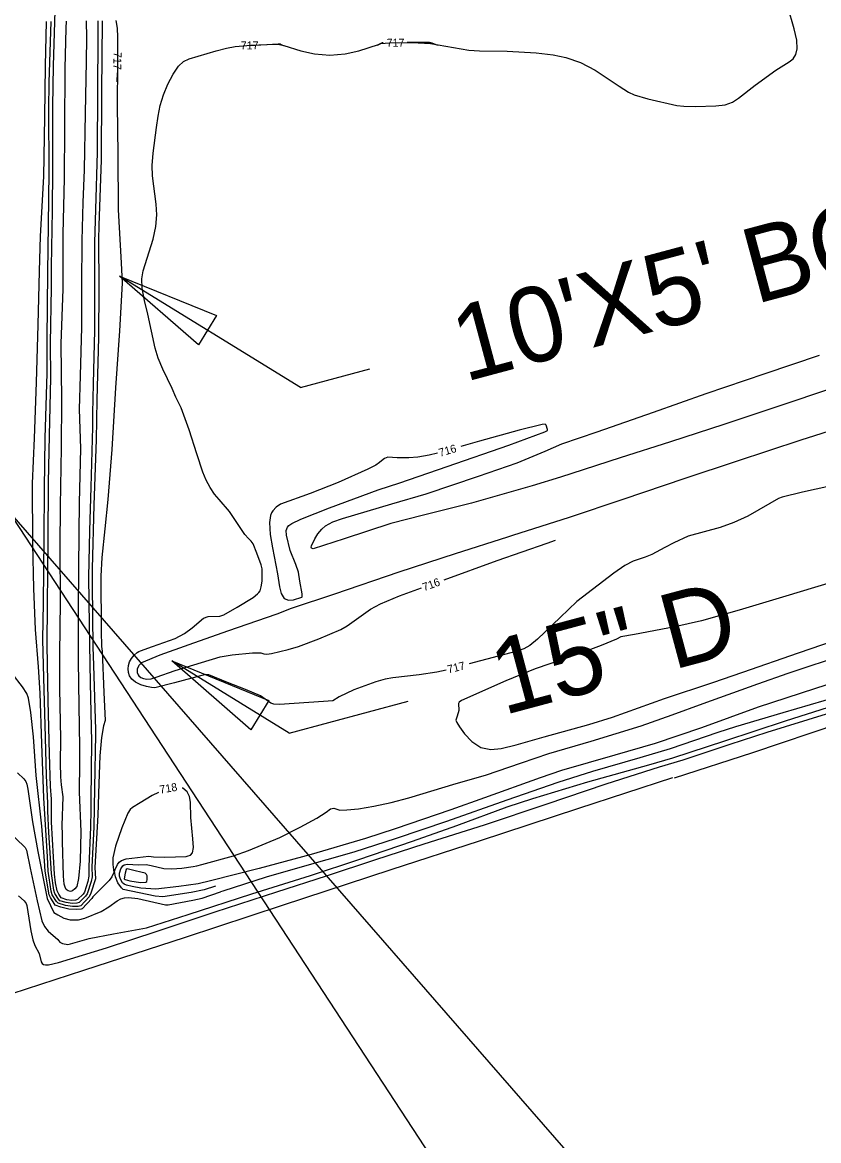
# Model space of a CAD drawing. Extents: x -361782338 to 28259792, y -263199453 to 8342113.
# Drawn here: x 1403847 to 1404244, y 576353 to 576912 of the extents above; entities that cross this region are included whole.
import ezdxf

# ---------------------------------------------------------------- set-up
doc = ezdxf.new("R2010")
doc.units = 0
for name, color, linetype in [('DT_X_Contour_Minor', 7, 'Continuous'), ('Level 14', 7, 'Continuous'), ('Level 19', 7, 'Continuous'), ('Level 40', 7, 'Continuous')]:
    doc.layers.add(name, color=color, linetype=linetype)

msp = doc.modelspace()

# ---------------------------------------------------------------- linework, layer by layer
at = {"layer": 'DT_X_Contour_Minor'}
for points in [[(1403884.36, 576912.33), (1403884.32, 576904.28), (1403884.16, 576877.16), (1403883.92, 576846.72), (1403883.03, 576818.05), (1403882.55, 576801.44), (1403882.6, 576772.64), (1403882.57, 576757.74), (1403881.87, 576730.96), (1403881.62, 576716.27), (1403881.61, 576709.28), (1403880.76, 576679.2), (1403880.08, 576657.35), (1403879.66, 576634.3), (1403879.9, 576610.47), (1403880.37, 576581.24), (1403881.17, 576552.15), (1403880.71, 576523.06), (1403880.85, 576518.07), (1403880.59, 576509.33), (1403879.73, 576489.71), (1403879.82, 576484.8), (1403879.32, 576482.14), (1403877.63, 576476.86), (1403876.9, 576475.86), (1403874.2, 576473.17), (1403873.16, 576472.81), (1403871.24, 576472.72), (1403868.84, 576473.06), (1403865.97, 576474.1), (1403864.78, 576475.79), (1403863.92, 576477.46), (1403863.17, 576481.55), (1403862.63, 576485.88), (1403861.15, 576511.91), (1403861.2, 576523.26), (1403860.67, 576529.64), (1403860.07, 576546.06), (1403859.55, 576572.43), (1403858.89, 576600.21), (1403859.22, 576620.7), (1403859.54, 576652.76), (1403859.67, 576681.58), (1403860.06, 576704.99), (1403860.76, 576733.86), (1403860.71, 576751.16), (1403861.07, 576778.81), (1403861.17, 576789.45), (1403861.6, 576817.44), (1403861.85, 576838.38), (1403861.82, 576869.5), (1403862.2, 576889.83), (1403863.02, 576917.3)], [(1403964.65, 576626.61), (1403965.31, 576627.48), (1403965.92, 576629.5), (1403966.28, 576632.33), (1403966.43, 576635.5), (1403966.3, 576638.36), (1403965.85, 576640.46), (1403963.61, 576646.32), (1403961.9, 576650.93), (1403960.82, 576652.32), (1403959.46, 576653.61), (1403957.69, 576655.65), (1403950.11, 576667.07), (1403944.88, 576673.03), (1403942.5, 576675.82), (1403940.34, 576679.05), (1403938.41, 576682.73), (1403936.72, 576686.75), (1403933.71, 576695.92), (1403929.94, 576707.86), (1403925.98, 576718.96), (1403923.93, 576722.94), (1403923.17, 576724.25), (1403921.39, 576728.58), (1403916.72, 576738.23), (1403914.47, 576743.66), (1403912.99, 576748.64), (1403909.25, 576765.72), (1403907.62, 576772.55), (1403906.49, 576778.64), (1403906.29, 576783.31), (1403906.96, 576787.28), (1403911.99, 576803.19), (1403913.32, 576809.49), (1403913.75, 576815.37), (1403913.49, 576820.75), (1403911.6, 576834.88), (1403911.45, 576840.08), (1403911.84, 576846.16), (1403913.5, 576859.02), (1403914.38, 576864.72), (1403915.46, 576870.01), (1403917.01, 576875.25), (1403919.23, 576880.65), (1403921.86, 576885.67), (1403924.55, 576889.61), (1403927.08, 576891.98), (1403929.85, 576893.31), (1403943.44, 576897.29), (1403948.53, 576898.59), (1403952.85, 576899.39), (1403960.67, 576900.06), (1403972.77, 576900.6), (1403975.09, 576900.47), (1403977.21, 576899.97), (1403985.63, 576897.33), (1403992.45, 576895.8), (1404000.1, 576895.11), (1404007.8, 576895.8), (1404014.71, 576897.32), (1404024.43, 576900.43), (1404025.57, 576900.9), (1404030.03, 576901.24), (1404041.26, 576901.39), (1404050.48, 576900.95), (1404069.63, 576897.69), (1404074.9, 576897.35), (1404088.73, 576897.06), (1404103.28, 576896.38), (1404111.62, 576895.36), (1404118.06, 576893.99), (1404125.29, 576891.47), (1404132.68, 576887.59), (1404144.62, 576879.6), (1404149.27, 576876.62), (1404152.18, 576875.33), (1404158.94, 576873.39), (1404173.48, 576870.04), (1404176.97, 576869.66), (1404182.84, 576869.52), (1404192.9, 576869.75), (1404197.68, 576870.4), (1404201.25, 576871.65), (1404204.3, 576873.63), (1404212.65, 576880.19), (1404222.98, 576887.58), (1404229.58, 576891.73), (1404231.57, 576893.35), (1404232.96, 576895.41), (1404233.61, 576898.34), (1404233.32, 576902.57), (1404232, 576908.22), (1404228.93, 576919.34)], [(1403893.32, 576912.46), (1403893.86, 576908.67), (1403894.13, 576904.07), (1403894.04, 576890.51), (1403893.91, 576870.17), (1403894.23, 576845.71), (1403894.45, 576817.91), (1403895.94, 576791.31), (1403896.47, 576781.23), (1403895.03, 576757.39), (1403893.14, 576728.83), (1403891.34, 576698.04), (1403889.25, 576673.14), (1403887.76, 576658.39), (1403886.21, 576644.17), (1403885.78, 576634.77), (1403885.96, 576607.37), (1403886.04, 576599.6), (1403886.48, 576597.33), (1403887.23, 576576.6), (1403887.89, 576562.6), (1403887.14, 576560.05), (1403886.12, 576554.11), (1403885.21, 576545.05), (1403884.7, 576531.11), (1403884.21, 576515.37), (1403882.7, 576489.2), (1403883.03, 576483.47), (1403880.75, 576476.31), (1403880.02, 576474.6), (1403875.71, 576470.11), (1403874.48, 576469.75), (1403871.69, 576469.69), (1403868.07, 576470.2), (1403864.43, 576471.32), (1403863.64, 576472.13), (1403861.5, 576475.52), (1403861.04, 576477.43), (1403859.54, 576487.29), (1403859.12, 576494.45), (1403857.26, 576523.99), (1403856.34, 576551.02), (1403855.53, 576576.32), (1403854.7, 576589.54), (1403853.21, 576608.11), (1403852.24, 576628.69), (1403851.85, 576650.85), (1403851.58, 576681.16), (1403852.64, 576703.71), (1403853.63, 576731.52), (1403854.4, 576760.3), (1403855.06, 576787.24), (1403855.7, 576804.65), (1403857.32, 576834.47), (1403857.73, 576864.36), (1403858.2, 576889.74), (1403858.66, 576911.96)], [(1403886.45, 576912.36), (1403886.28, 576894.22), (1403886.19, 576876.96), (1403885.87, 576842.84), (1403884.83, 576809.99), (1403884.69, 576803.05), (1403884.74, 576778.83), (1403884.61, 576754.03), (1403883.83, 576722.91), (1403883.38, 576702.96), (1403882.35, 576670.47), (1403881.37, 576638.44), (1403881.39, 576630.37), (1403881.81, 576599.25), (1403882.04, 576590.28), (1403883.19, 576557.97), (1403883.19, 576555.64), (1403882.69, 576528.92), (1403882.2, 576509.33), (1403881.21, 576489.45), (1403881.49, 576484.54), (1403881, 576482.2), (1403879, 576476.04), (1403878.17, 576474.91), (1403874.96, 576471.64), (1403873.82, 576471.28), (1403871.46, 576471.21), (1403868.45, 576471.63), (1403865.38, 576472.59), (1403864.64, 576473.3), (1403862.8, 576476.22), (1403862.38, 576477.9), (1403861.1, 576486.22), (1403859.84, 576506.61), (1403859.31, 576517.37), (1403859.38, 576521.26), (1403858.63, 576535.2), (1403858.01, 576560.26), (1403857.26, 576584), (1403856.8, 576603.13), (1403857.09, 576621.48), (1403857.54, 576653.89), (1403857.64, 576678.29), (1403857.97, 576703.79), (1403858.92, 576736.27), (1403858.97, 576753.05), (1403859.24, 576786.75), (1403859.6, 576810.33), (1403859.92, 576836.88), (1403859.8, 576868.15), (1403860.01, 576881.43), (1403860.92, 576911.99)], [(1403878.48, 576912.25), (1403878.54, 576903.78), (1403878.45, 576891.99), (1403877.96, 576866.15), (1403877.47, 576837.79), (1403876.86, 576821.44), (1403876.22, 576802.58), (1403876.12, 576780.28), (1403876.19, 576759.14), (1403875.38, 576734.9), (1403874.9, 576718.28), (1403875.63, 576698.54), (1403875.02, 576671.43), (1403874.85, 576656.6), (1403874.7, 576638.11), (1403874.43, 576618.15), (1403874.45, 576592.48), (1403874.76, 576569.92), (1403875.14, 576549.46), (1403875.1, 576541.67), (1403875.03, 576526.78), (1403875.74, 576507.12), (1403875.4, 576492.38), (1403874.55, 576483.66), (1403873.72, 576479.67), (1403872.85, 576478.47), (1403871.55, 576477.54), (1403870.55, 576477.27), (1403869.43, 576477.55), (1403868.49, 576478.21), (1403867.88, 576479.37), (1403867.53, 576480.87), (1403867.2, 576484.83), (1403866.62, 576502.24), (1403866.55, 576505.73), (1403866.54, 576510.18), (1403866.91, 576524.51), (1403866.18, 576530.48), (1403865.74, 576534.45), (1403865.69, 576541.29), (1403865.74, 576553.52), (1403865.24, 576578.63), (1403865.24, 576595.93), (1403865.62, 576621.8), (1403865.53, 576649.36), (1403865.7, 576669.88), (1403866.15, 576698.99), (1403866.36, 576722.94), (1403866.01, 576751.07), (1403866.97, 576778.26), (1403867, 576805.86), (1403867.61, 576833.53), (1403867.78, 576858.87), (1403868.04, 576888.4), (1403868.4, 576908.63), (1403868.55, 576912.1)], [(1403960, 576900), (1403974.39, 576900.85), (1403974.69, 576900.85), (1403974.99, 576900.81), (1403975.27, 576900.73), (1403975.55, 576900.62), (1403976.83, 576900)], [(1404026.87, 576901.27), (1404026.68, 576901.27), (1404026.47, 576901.25), (1404026.27, 576901.22), (1404026.08, 576901.17), (1404025.88, 576901.09), (1404025.13, 576900.76), (1404025.07, 576900.72), (1404025, 576900.69), (1404024.94, 576900.65), (1404024.88, 576900.6), (1404024.7, 576900.44), (1404024.66, 576900.41), (1404024.62, 576900.38), (1404024.57, 576900.35), (1404024.53, 576900.33), (1404023.75, 576900)], [(1404054.03, 576899.99), (1404051.2, 576901.08), (1404050.59, 576901.29), (1404049.97, 576901.43), (1404049.34, 576901.51), (1404048.7, 576901.53), (1404038.86, 576901.42)], [(1403893.88, 576886.39), (1403893.73, 576881.81)], [(1404249.74, 576728.19), (1404225.37, 576720.01), (1404196.87, 576710.58), (1404170.25, 576701.97), (1404145.18, 576693.96), (1404120.97, 576686.1), (1404115.35, 576684.17), (1404101.21, 576679.91), (1404070.85, 576671.32), (1404046.9, 576665.34), (1404030.62, 576661.08), (1404007.35, 576653.44), (1403991.76, 576648.35), (1403991.05, 576648.75), (1403990.81, 576649.26), (1403990.94, 576649.93), (1403992.65, 576653.42), (1403994.24, 576655.95), (1403996.09, 576658.3), (1403998.02, 576660), (1404001.7, 576661.94), (1404006.5, 576663.61), (1404031.1, 576670.87), (1404048.34, 576675.99), (1404074.47, 576684.83), (1404093.68, 576691.47), (1404107.71, 576697.3), (1404116.09, 576700.83), (1404133.67, 576706.98), (1404161.78, 576716.79), (1404188.09, 576725.99), (1404217.54, 576736.11), (1404244.66, 576745.26)], [(1404343.7, 576737.72), (1404328.98, 576732.82), (1404301.91, 576724.01), (1404287.5, 576719.5), (1404263.17, 576711.61), (1404235.45, 576702.71), (1404203.09, 576692.14), (1404177.51, 576683.51), (1404146.48, 576673.07), (1404119.69, 576664.09), (1404091.39, 576655.12), (1404088.86, 576654.3)], [(1403985.19, 576632.29), (1403984.45, 576636.74), (1403983.16, 576640.65), (1403980.28, 576647.55), (1403978.56, 576655.2), (1403978.35, 576657.52), (1403978.94, 576659.2), (1403979.74, 576660.12), (1403981.11, 576661.1), (1403985.62, 576663.21), (1403999.99, 576668.99), (1404024.26, 576677.89), (1404035.11, 576681.45), (1404058.79, 576689.56), (1404089.51, 576700.28), (1404107.52, 576706.9), (1404108.8, 576707.57), (1404108.85, 576708.06), (1404108.13, 576710.29), (1404107.74, 576710.73), (1404106.14, 576710.61), (1404094.67, 576707.73), (1404074.87, 576702.21), (1404065.53, 576699.51)], [(1404053.97, 576696.28), (1404049.82, 576695.24), (1404044.08, 576694.25), (1404039.6, 576693.86), (1404033.78, 576693.91), (1404029.04, 576694.18), (1404027.5, 576693.59), (1404025.89, 576692.37), (1404025.01, 576691.55), (1404023.11, 576690.27), (1404019.13, 576688.17), (1404004.28, 576681.59), (1403990.27, 576676.07), (1403975.53, 576670.83), (1403973.31, 576669.2), (1403971.7, 576667.44), (1403971.01, 576666.38), (1403970.49, 576665.04), (1403970.1, 576661.57), (1403970.3, 576655.6), (1403971.46, 576648.91), (1403974.04, 576635.97), (1403974.98, 576629.46)], [(1404265.11, 576683.16), (1404236.15, 576676.75), (1404226.06, 576674.23), (1404224.23, 576673.56), (1404219.95, 576671.1), (1404208.92, 576664.77), (1404201.99, 576661.54), (1404195.05, 576659.15), (1404179.2, 576654.73), (1404171.98, 576651.4), (1404167.46, 576649.17), (1404161, 576645.68), (1404157.72, 576644.21), (1404151.59, 576642.2), (1404147.45, 576640.04), (1404141.96, 576636.25), (1404123.56, 576622.13), (1404115.23, 576614.16), (1404103.82, 576603.27), (1404100.08, 576600.15), (1404097, 576598.45), (1404093.12, 576597.18), (1404069.82, 576590.89)], [(1404088.86, 576654.3), (1404062.82, 576645.94), (1404034.67, 576636.74), (1404002.44, 576625.8), (1403980.81, 576618.62), (1403973.71, 576615.84), (1403949.1, 576607.23), (1403929.7, 576600.39), (1403915.31, 576595.36), (1403906.11, 576591.51), (1403904.73, 576590.07), (1403904.6, 576589.76)], [(1404057.21, 576632.97), (1404083.8, 576642.59), (1404108.64, 576651.26), (1404112.92, 576652.74)], [(1403974.98, 576629.46), (1403974.99, 576629.38), (1403975.84, 576626.04), (1403977.3, 576623.65), (1403979.54, 576622.77), (1403982.06, 576622.96), (1403986.21, 576624.2), (1403986.4, 576624.5), (1403986.26, 576625.87), (1403985.19, 576632.29)], [(1404258.2, 576633.89), (1404227.89, 576624.76), (1404204.67, 576617.85), (1404185.83, 576612.39), (1404172.54, 576609.45), (1404152.34, 576605.62), (1404145.51, 576604.46), (1404143.27, 576603.34), (1404135.65, 576600.19), (1404124.16, 576595.86), (1404102.69, 576588.46), (1404088.12, 576582.55), (1404065.99, 576572.63), (1404064.7, 576571.88), (1404064.41, 576571.21), (1404064.63, 576567.56), (1404063.79, 576564.83), (1404063.12, 576562.86), (1404063.53, 576561.66), (1404064.88, 576559.48), (1404067.44, 576555.98), (1404071.08, 576552.13), (1404075.58, 576549.22), (1404080.64, 576548.2), (1404085.67, 576548.59), (1404093.27, 576550.47), (1404107.23, 576554.43), (1404129.46, 576560.57), (1404141.31, 576564.35), (1404167.24, 576573.66), (1404191.45, 576581.68), (1404206.47, 576586.77), (1404234.28, 576596.46), (1404258, 576604.67)], [(1403904.5, 576585.42), (1403904.81, 576584.94), (1403905.71, 576584.21), (1403907.03, 576583.64), (1403908.78, 576583.36), (1403910.94, 576583.54), (1403913.48, 576584.26), (1403922.91, 576587.66), (1403945.46, 576594.48), (1403951.4, 576595.5), (1403961.59, 576596.5), (1403965.67, 576596.42), (1403967.24, 576595.94), (1403968.61, 576595.87), (1403970.99, 576596.14), (1403979.31, 576598.1), (1403984.46, 576599.69), (1403994.59, 576603.52), (1404005.71, 576608.13), (1404008.8, 576609.93), (1404020.44, 576618.24), (1404025.42, 576620.87), (1404035, 576624.88), (1404045.94, 576628.87)], [(1403904.77, 576597.06), (1403905.61, 576597.52), (1403911.51, 576599.56), (1403922.93, 576603.67), (1403927.63, 576606.1), (1403931.44, 576608.96), (1403937.01, 576613.77), (1403939.32, 576614.63), (1403945.13, 576614.79), (1403947.18, 576615.53), (1403953.91, 576619.2), (1403961.78, 576624.1), (1403964.09, 576625.87), (1403964.65, 576626.61)], [(1403904.4, 576581.12), (1403903.09, 576581.73), (1403901.26, 576583.23), (1403900.15, 576584.9), (1403899.58, 576586.67), (1403899.4, 576588.43), (1403899.59, 576590.18), (1403900.16, 576591.93), (1403901.1, 576593.66), (1403902.37, 576595.26), (1403903.9, 576596.58), (1403904.77, 576597.06)], [(1403933.74, 576490.07), (1403936.21, 576490.63), (1403951.99, 576494.97), (1403959.53, 576497.76), (1403975.25, 576504.2), (1403985.41, 576509.31), (1403993.64, 576513.82), (1403998.38, 576516.91), (1404000.53, 576518.47), (1404002.2, 576518.79), (1404005.22, 576517.88), (1404008.58, 576517.93), (1404014.4, 576518.55), (1404022.1, 576519.79), (1404030.78, 576521.65), (1404039.62, 576524.05), (1404063.21, 576531.14), (1404077.86, 576535.36), (1404095.8, 576541.47), (1404109.58, 576546.15), (1404130.74, 576552.39), (1404155.63, 576560.01), (1404171.17, 576565.54), (1404186.57, 576571.13), (1404213.84, 576580.95), (1404229.05, 576586.24), (1404258.24, 576595.98)], [(1403905.35, 576521.43), (1403901.61, 576519.13), (1403900.44, 576518.15), (1403899.24, 576516.28), (1403896.2, 576509.05), (1403893.05, 576499.9), (1403891.71, 576494.08), (1403891.73, 576490.6), (1403892.31, 576486.71), (1403891.26, 576484.44), (1403889.9, 576482.63), (1403885.47, 576478.22), (1403881.82, 576474.47), (1403881.34, 576473.66), (1403876.47, 576468.59), (1403875.94, 576468.31), (1403873.77, 576468.17), (1403869.82, 576468.36), (1403865.76, 576469.3), (1403863.05, 576470.36), (1403860.57, 576474.16), (1403859.96, 576475.56), (1403858.03, 576487.31), (1403857.7, 576492.44), (1403856.28, 576509.8), (1403853.46, 576535.23), (1403852.17, 576554.47), (1403850.88, 576566.66), (1403849.71, 576573.81), (1403848.76, 576576.22), (1403846.72, 576579.41), (1403841.51, 576586.1)], [(1403904.6, 576589.76), (1403903.99, 576588.36), (1403903.98, 576586.64), (1403904.26, 576585.77), (1403904.5, 576585.42)], [(1404058.2, 576587.88), (1404053.6, 576586.73), (1404044.72, 576585.4), (1404031.64, 576584.02), (1404027.71, 576583.23), (1404023.17, 576581.94), (1404012.13, 576577.89), (1404004.74, 576574.4), (1404001.61, 576572.47), (1403996.99, 576572.06), (1403974.98, 576570.61), (1403972.11, 576570.81), (1403970.76, 576571.33), (1403965.47, 576575.01), (1403957.96, 576578.07), (1403948.96, 576581.64), (1403939.76, 576585.46), (1403938.05, 576585.62), (1403922.59, 576581.47), (1403912.78, 576578.98), (1403911.02, 576579.1), (1403908.54, 576579.63), (1403905.69, 576580.52), (1403904.4, 576581.12)], [(1404265.37, 576586.02), (1404242.23, 576578.4), (1404214.06, 576569.28), (1404185.71, 576559.02), (1404162.72, 576551.15), (1404142.42, 576545.31), (1404115.78, 576537.64), (1404105.18, 576534.01), (1404077.48, 576523.97), (1404060.59, 576518.02), (1404032.73, 576508.49), (1404017.92, 576503.69), (1403990.88, 576495.74), (1403964.81, 576488.74), (1403940.55, 576482.54)], [(1404253.63, 576574.49), (1404226.33, 576566.45), (1404202.69, 576559.49), (1404193.93, 576556.65), (1404170.16, 576548.53), (1404154.94, 576543.94), (1404131.42, 576537.1), (1404113.99, 576531.6), (1404088.56, 576522.75), (1404058.45, 576512.11), (1404033.22, 576503.64), (1404012.17, 576496.85), (1403985.21, 576489.12), (1403968.41, 576484.42), (1403946.68, 576477.31), (1403945.61, 576476.96)], [(1403838.76, 576507.99), (1403848.06, 576499.21), (1403848.57, 576497.8), (1403850.51, 576488.86), (1403853.96, 576472.54), (1403856.36, 576462.55), (1403857.64, 576459.63), (1403859.51, 576457.29), (1403864.28, 576453.12), (1403865.23, 576451.81), (1403866.66, 576451.19), (1403869.24, 576450.76), (1403870.57, 576450.99), (1403879.93, 576453.63), (1403892.17, 576456.03), (1403908.58, 576458.96), (1403929.43, 576465.76), (1403961.13, 576476.06), (1403990.51, 576485.26), (1404014.65, 576493.26), (1404041.45, 576502.39), (1404063.59, 576510.22), (1404088.76, 576519.56), (1404101.62, 576523.64), (1404128.99, 576532.01), (1404159.47, 576540.57), (1404171.44, 576544.04), (1404197.4, 576552.44), (1404227.72, 576562.44), (1404249.17, 576569.31)], [(1403844.68, 576475.03), (1403847.54, 576472.53), (1403848.53, 576471.27), (1403848.87, 576470.15), (1403850.89, 576457.5), (1403851.87, 576453.07), (1403852.87, 576450.27), (1403855, 576446.15), (1403855.92, 576442.06), (1403856.41, 576441.26), (1403857.12, 576440.75), (1403858.15, 576440.51), (1403859.63, 576440.58), (1403864.57, 576441.79), (1403888.62, 576449.07), (1403913.85, 576457.39), (1403942.8, 576467.01), (1403973.72, 576477.05), (1403998.41, 576485.04), (1404023.19, 576493.23), (1404047.28, 576500.98), (1404077.41, 576510.54), (1404108.28, 576520.77), (1404138.13, 576530.94), (1404164.89, 576539.51), (1404176.64, 576542.99), (1404200.06, 576550.77), (1404218.66, 576556.83), (1404248.17, 576565.9)], [(1403844.13, 576536.5), (1403847.36, 576533.45), (1403848.38, 576532.13), (1403848.85, 576530.87), (1403849.34, 576528.4), (1403851.58, 576511.97), (1403854.3, 576497.25), (1403858.98, 576473.69), (1403862.27, 576466.69), (1403864.27, 576465.45), (1403867.3, 576463.94), (1403870.47, 576463.06), (1403874.62, 576462.95), (1403877.8, 576463.93), (1403886.01, 576467.17), (1403889.75, 576469.55), (1403893.87, 576472.51), (1403895.76, 576473.52), (1403897.63, 576474.1), (1403899.67, 576474.26), (1403904.2, 576473.65), (1403918.07, 576470.54), (1403919.47, 576470.59), (1403931.71, 576472.88), (1403936.35, 576473.93), (1403945.61, 576476.96)], [(1403929.33, 576494.94), (1403930.59, 576495.32), (1403931.57, 576496.53), (1403932.04, 576499.15), (1403931.8, 576503.55), (1403930.65, 576514.17), (1403930.52, 576521.82), (1403930.09, 576524.62), (1403928.84, 576527.05), (1403926.69, 576528.81), (1403926.35, 576528.88)], [(1403914.54, 576526.74), (1403911.36, 576525.13), (1403905.35, 576521.43)], [(1403943.01, 576479.83), (1403937.33, 576478.06), (1403930.82, 576476.65), (1403916.7, 576474.48), (1403912.96, 576474.87), (1403896.89, 576478.27), (1403896.06, 576478.94), (1403894.33, 576481.5), (1403893.14, 576484.52), (1403892.66, 576487.22), (1403892.94, 576488.24), (1403894.04, 576490.61), (1403894.96, 576491.83), (1403896.11, 576492.72), (1403898.39, 576493.56), (1403909.79, 576494.93), (1403912.12, 576494.55), (1403917.7, 576494.41), (1403928.45, 576494.68), (1403929.33, 576494.94)], [(1403940.55, 576482.54), (1403934.37, 576480.96), (1403924.7, 576479.62), (1403913.33, 576478.33), (1403905.69, 576478.9), (1403901.43, 576479.71), (1403898.6, 576480.39), (1403897.44, 576480.9), (1403896.57, 576481.59), (1403895.53, 576483.28), (1403895.13, 576484.9), (1403895.16, 576486.33), (1403895.81, 576488.59), (1403896.72, 576490.09), (1403897.38, 576490.57), (1403899.14, 576490.9), (1403904.34, 576490.53), (1403908.34, 576490.73), (1403910.98, 576490.19), (1403917.23, 576488.75), (1403921.19, 576488.5), (1403926.21, 576488.89), (1403931.82, 576489.63), (1403933.74, 576490.07)], [(1403898.92, 576488.56), (1403898.36, 576488.18), (1403897.89, 576486.42), (1403897.45, 576483.52), (1403897.95, 576483.12), (1403900.32, 576482.52), (1403905.66, 576481.64), (1403908.24, 576481.93), (1403908.71, 576482.2), (1403908.99, 576483.23), (1403908.94, 576484.97), (1403908.59, 576485.76), (1403907.91, 576486.3), (1403905.76, 576486.84), (1403902.92, 576487.47), (1403898.92, 576488.56)]]:
    msp.add_lwpolyline(points, dxfattribs=at)
at = {"layer": 'Level 14'}
for points in [[(1404683.02, 576699.67), (1404638.14, 576685.26), (1404590.07, 576669.58), (1404543.76, 576654.5), (1404494.13, 576638.59), (1404446.54, 576623.29), (1404397.76, 576607.63), (1404352.95, 576593.18), (1404303.34, 576577.07), (1404254.75, 576561.14), (1404211.28, 576546.5), (1404172.05, 576533.75)], [(1404171.22, 576533.92), (1404124.32, 576518.59), (1404074.79, 576502.42), (1404030.68, 576487.94), (1403976.28, 576470.16), (1403927.93, 576454.25), (1403877.13, 576437.7), (1403798.15, 576412.11), (1403755.23, 576398.08), (1403707.95, 576382.82)]]:
    msp.add_lwpolyline(points, dxfattribs=at)
at = {"layer": 'Level 40'}
for p, q in [((1403985.56, 576729.05), (1403895.08, 576784.74)), ((1403934.5, 576750.39), (1403895.08, 576784.74)), ((1403895.08, 576784.74), (1403943.5, 576765.01)), ((1403943.5, 576765.01), (1403934.5, 576750.39)), ((1403985.56, 576729.05), (1404020.16, 576738.33)), ((1403979.87, 576556.32), (1403921.28, 576592.38)), ((1403960.7, 576558.02), (1403921.28, 576592.38)), ((1403921.28, 576592.38), (1403969.7, 576572.65)), ((1403969.7, 576572.65), (1403960.7, 576558.02)), ((1403979.87, 576556.32), (1404039.31, 576572.25))]:
    msp.add_line(p, q, dxfattribs=at)
msp.add_lwpolyline([(1404224.44, 576225.83), (1403839.07, 576668.32), (1404142.69, 576203.92)], close=True, dxfattribs=at)

# ---------------------------------------------------------------- texts
at = {"layer": 'Level 19'}
for s, rotation, p in [('717', 0.6936, (1404028.51, 576899.29)), ('717', 268.1156, (1403892.22, 576896.82)), ('716', 16.1402, (1404055.18, 576694.43)), ('716', 20.0249, (1404047.23, 576627.21)), ('717', 14.1062, (1404059.41, 576586.13)), ('718', 9.597, (1403915.42, 576526.08))]:
    msp.add_text(s, height=4, rotation=rotation, dxfattribs=at).set_placement(p)
msp.add_text('717', height=4, dxfattribs=at).set_placement((1403955.62, 576898))
at = {"layer": 'Level 40'}
for s, p in [("10'X5' BOX", (1404067.53, 576731.75)), ('15" D', (1404086.82, 576565.18))]:
    msp.add_text(s, height=37.5, rotation=15, dxfattribs=at).set_placement(p)

doc.saveas('drawing.dxf')
